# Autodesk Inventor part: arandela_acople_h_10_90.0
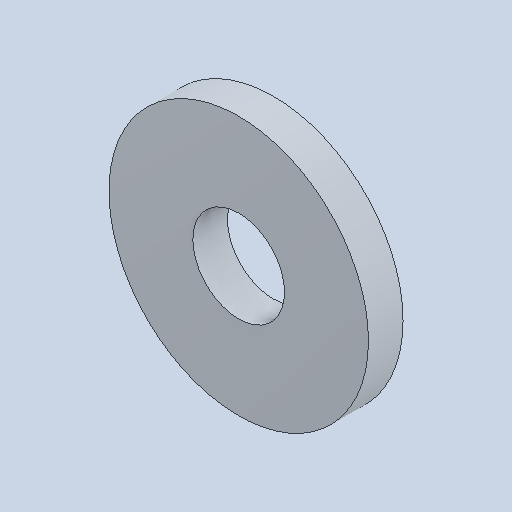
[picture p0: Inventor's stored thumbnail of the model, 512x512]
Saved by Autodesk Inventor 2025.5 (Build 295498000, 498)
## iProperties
Created: 2026-10
Part Number: arandela_acople_h_10_90.0
Material: Genérico
Document SubType Name: Modeling
Designer: Luis M
Density: 1 g/cm^3
Appearance: Valor por defecto
Author: Luis M
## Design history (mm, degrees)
feature "Base1"
node "Sólido1"
